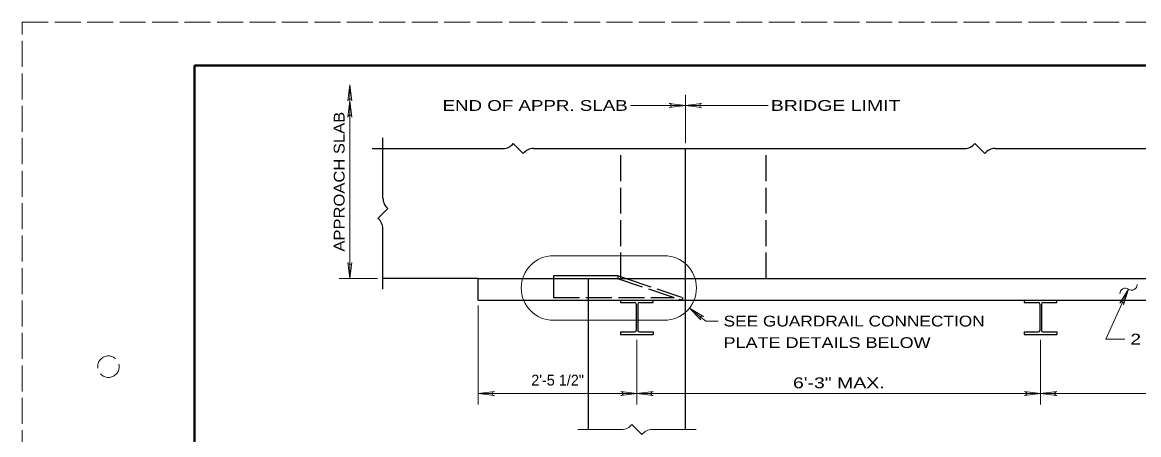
# Model space of a CAD drawing. Extents: x 1285 to 1427, y 1365 to 1427.
# Drawn here: x 1333.33 to 1350.62, y 1420.28 to 1426.67 of the extents above; entities that cross this region are included whole.
import ezdxf
from ezdxf.enums import TextEntityAlignment as Align

# ---------------------------------------------------------------- set-up
doc = ezdxf.new("R2010")
doc.units = 0
doc.header["$LTSCALE"] = 0.067
doc.linetypes.add('LONG_DASHED', pattern=[7.5, 6, -1.5])
for name, color, linetype, lineweight in [('1', 7, 'Continuous', 40), ('42', 7, 'Continuous', 25), ('43', 7, 'Continuous', 25), ('44', 7, 'Continuous', 13), ('47', 7, 'Continuous', 13), ('50', 7, 'LONG_DASHED', 13)]:
    doc.layers.add(name, color=color, linetype=linetype, lineweight=lineweight)
doc.layers.add('41', color=7, linetype='Continuous')

msp = doc.modelspace()

# ---------------------------------------------------------------- linework, layer by layer
at = {"layer": '1', "linetype": 'LONG_DASHED', "lineweight": 13}
msp.add_lwpolyline([(1333.33333, 1426.66667), (1378.66667, 1426.66667), (1378.66667, 1397.33333), (1333.33333, 1397.33333)], close=True, dxfattribs=at)
at = {"layer": '1'}
msp.add_lwpolyline([(1336, 1426), (1378, 1426), (1378, 1398), (1336, 1398)], close=True, dxfattribs=at)
at = {"layer": '42'}
for p, q in [((1338.91656, 1423.94189), (1338.91656, 1424.87889)), ((1340.93544, 1424.78967), (1341.09011, 1424.63478)), ((1348.08167, 1424.78967), (1348.23633, 1424.63478)), ((1338.74989, 1424.71222), (1340.778, 1424.71222)), ((1341.24844, 1424.71222), (1347.92233, 1424.71222)), ((1343.59989, 1422.69833), (1343.59989, 1424.71222)), ((1348.39467, 1424.71222), (1353.05289, 1424.71222)), ((1338.994, 1423.78256), (1338.83911, 1423.62789)), ((1338.91656, 1422.53167), (1338.91656, 1423.46956)), ((1340.39156, 1422.69833), (1338.91656, 1422.69833)), ((1340.39156, 1422.69833), (1356.50211, 1422.69833)), ((1340.39156, 1422.365), (1340.39156, 1422.69833)), ((1341.55756, 1422.69833), (1342.55067, 1422.69833)), ((1342.55756, 1422.74), (1342.55067, 1422.69833)), ((1342.55756, 1422.74), (1342.68256, 1422.69833)), ((1340.39156, 1422.365), (1356.50211, 1422.365)), ((1342.09989, 1420.36067), (1342.09989, 1422.365)), ((1342.59656, 1422.365), (1343.10322, 1422.365)), ((1342.59656, 1422.365), (1342.59656, 1422.32711)), ((1343.10322, 1422.32711), (1343.10322, 1422.365)), ((1343.59989, 1420.36067), (1343.59989, 1422.365)), ((1348.84656, 1422.365), (1349.35322, 1422.365)), ((1348.84656, 1422.365), (1348.84656, 1422.32711)), ((1349.35322, 1422.32711), (1349.35322, 1422.365)), ((1342.59656, 1422.32711), (1342.81322, 1422.32711)), ((1342.83656, 1422.30378), (1342.83656, 1421.89456)), ((1342.86322, 1422.30378), (1342.86322, 1421.89456)), ((1342.88656, 1422.32711), (1343.10322, 1422.32711)), ((1348.84656, 1422.32711), (1349.06322, 1422.32711)), ((1349.08656, 1422.30378), (1349.08656, 1421.89456)), ((1349.11322, 1422.30378), (1349.11322, 1421.89456)), ((1349.13656, 1422.32711), (1349.35322, 1422.32711)), ((1342.59656, 1421.87122), (1342.59656, 1421.83333)), ((1342.59656, 1421.87122), (1342.81322, 1421.87122)), ((1342.59656, 1421.83333), (1343.10322, 1421.83333)), ((1342.88656, 1421.87122), (1343.10322, 1421.87122)), ((1343.10322, 1421.87122), (1343.10322, 1421.83333)), ((1348.84656, 1421.87122), (1348.84656, 1421.83333)), ((1348.84656, 1421.87122), (1349.06322, 1421.87122)), ((1348.84656, 1421.83333), (1349.35322, 1421.83333)), ((1349.13656, 1421.87122), (1349.35322, 1421.87122)), ((1349.35322, 1421.87122), (1349.35322, 1421.83333))]:
    msp.add_line(p, q, dxfattribs=at)
msp.add_lwpolyline([(1342.55756, 1422.74), (1341.55756, 1422.74), (1341.55756, 1422.69833)], dxfattribs=at)
for centre, radius, start, end in [((1340.77707, 1424.91285), 0.20062, 270, 322.10148), ((1347.9233, 1424.91285), 0.20062, 270, 322.10148), ((1341.24848, 1424.51159), 0.20062, 90, 142.10148), ((1348.3947, 1424.51159), 0.20062, 90, 142.10148), ((1339.11718, 1423.94093), 0.20062, 180, 232.10148), ((1338.71593, 1423.46952), 0.20062, 360, 52.10148), ((1342.81322, 1422.30378), 0.02333, 0, 90), ((1342.88656, 1422.30378), 0.02333, 90, 180), ((1349.06322, 1422.30378), 0.02333, 0, 90), ((1349.13656, 1422.30378), 0.02333, 90, 180), ((1342.81322, 1421.89456), 0.02333, 270, 0), ((1342.88656, 1421.89456), 0.02333, 180, 270), ((1349.06322, 1421.89456), 0.02333, 270, 0), ((1349.13656, 1421.89456), 0.02333, 180, 270)]:
    msp.add_arc(centre, radius, start, end, dxfattribs=at)
at = {"layer": '43', "linetype": 'LONG_DASHED'}
for p, q in [((1342.59989, 1422.69833), (1342.59989, 1424.71222)), ((1344.84989, 1422.69833), (1344.84989, 1424.71222)), ((1342.09989, 1422.365), (1342.09989, 1422.69833)), ((1342.55067, 1422.69833), (1343.54433, 1422.36711)), ((1342.68256, 1422.69833), (1343.55756, 1422.40667)), ((1343.59989, 1422.365), (1343.59989, 1422.69833)), ((1343.55756, 1422.40667), (1343.54433, 1422.36711))]:
    msp.add_line(p, q, dxfattribs=at)
msp.add_lwpolyline([(1341.55756, 1422.69833), (1341.55756, 1422.40667), (1343.42567, 1422.40667)], dxfattribs=at)
at = {"layer": '44'}
for p, q in [((1343.59989, 1425.37889), (1342.74789, 1425.37889)), ((1343.59989, 1425.37889), (1343.34989, 1425.41011)), ((1343.84989, 1425.41011), (1343.59989, 1425.37889)), ((1343.59989, 1425.37889), (1343.84989, 1425.34767)), ((1342.77256, 1420.43811), (1342.92722, 1420.28322))]:
    msp.add_line(p, q, dxfattribs=at)
msp.add_lwpolyline([(1343.34989, 1425.34767), (1343.59989, 1425.37889), (1344.88033, 1425.37889)], dxfattribs=at)
for centre, radius, start, end in [((1343.34989, 1425.37889), 0.03122, 270, 90), ((1343.84989, 1425.37889), 0.03122, 90, 270), ((1342.61419, 1420.56129), 0.20062, 270, 322.10148), ((1343.08559, 1420.16004), 0.20062, 90, 142.10148)]:
    msp.add_arc(centre, radius, start, end, dxfattribs=at)
at = {"layer": '47'}
for p, q in [((1338.40578, 1422.69833), (1338.40578, 1425.69833)), ((1343.59989, 1424.79556), (1343.59989, 1425.54556)), ((1341.55756, 1423.05244), (1343.271, 1423.05244)), ((1338.83322, 1422.69833), (1338.23911, 1422.69833)), ((1340.39156, 1422.28167), (1340.39156, 1420.75)), ((1341.55756, 1422.05244), (1343.271, 1422.05244)), ((1342.84989, 1421.75), (1342.84989, 1420.75)), ((1349.09989, 1421.75), (1349.09989, 1420.75)), ((1340.39156, 1420.91667), (1342.84989, 1420.91667)), ((1342.84989, 1420.91667), (1349.09989, 1420.91667)), ((1349.09989, 1420.91667), (1355.34989, 1420.91667)), ((1341.93322, 1420.36067), (1342.61322, 1420.36067)), ((1343.08556, 1420.36067), (1343.76656, 1420.36067))]:
    msp.add_line(p, q, dxfattribs=at)
for points in [[(1338.37456, 1425.44833), (1338.40578, 1425.69833), (1338.437, 1425.44833)], [(1338.37456, 1425.19833), (1338.40578, 1425.44833), (1338.437, 1425.19833)], [(1343.84989, 1425.34767), (1343.59989, 1425.37889), (1343.84989, 1425.41011)], [(1338.437, 1422.94833), (1338.40578, 1422.69833), (1338.37456, 1422.94833)], [(1350.40411, 1421.75967), (1350.10967, 1421.75967), (1350.45989, 1422.53333)], [(1350.32833, 1422.31844), (1350.45989, 1422.53333), (1350.38522, 1422.29267)], [(1344.10733, 1422.03956), (1343.91578, 1422.03956), (1343.66233, 1422.24111)], [(1343.83856, 1422.06111), (1343.66233, 1422.24111), (1343.87744, 1422.10989)], [(1340.64156, 1420.88544), (1340.39156, 1420.91667), (1340.64156, 1420.94789)], [(1342.59989, 1420.94789), (1342.84989, 1420.91667), (1342.59989, 1420.88544)], [(1343.09989, 1420.88544), (1342.84989, 1420.91667), (1343.09989, 1420.94789)], [(1348.84989, 1420.94789), (1349.09989, 1420.91667), (1348.84989, 1420.88544)], [(1349.34989, 1420.88544), (1349.09989, 1420.91667), (1349.34989, 1420.94789)]]:
    msp.add_lwpolyline(points, dxfattribs=at)
for centre, radius, start, end in [((1338.40584, 1425.44836), 0.03122, 0, 180), ((1343.84986, 1425.37895), 0.03122, 90, 270), ((1338.40584, 1425.19836), 0.03122, 0, 180), ((1341.55756, 1422.55244), 0.5, 90, 270), ((1343.27104, 1422.55244), 0.5, 270, 90), ((1338.40572, 1422.9483), 0.03122, 180, 0), ((1350.41073, 1422.46604), 0.08333, 53.85214, 183.85214), ((1350.50904, 1422.60062), 0.08333, 233.85214, 3.85214), ((1350.35686, 1422.30559), 0.03122, 335.64476, 155.64476), ((1343.85801, 1422.08557), 0.03122, 51.50599, 231.50599), ((1340.64152, 1420.91672), 0.03122, 90, 270), ((1342.59992, 1420.91661), 0.03122, 270, 90), ((1343.09986, 1420.91672), 0.03122, 90, 270), ((1348.84992, 1420.91661), 0.03122, 270, 90), ((1349.34986, 1420.91672), 0.03122, 90, 270)]:
    msp.add_arc(centre, radius, start, end, dxfattribs=at)
at = {"layer": '50'}
msp.add_circle((1334.66667, 1421.33333), 0.16667, dxfattribs=at)

# ---------------------------------------------------------------- texts
at = {"layer": '41', "width": 1.15}
msp.add_text('APPROACH SLAB', height=0.1667, rotation=90, dxfattribs=at).set_placement((1338.32244, 1424.19839), align=Align.CENTER)
at = {"layer": '41'}
for s, width, p in [('SEE GUARDRAIL CONNECTION ', 1.2, (1344.19067, 1421.95622)), ('2 - TS 8 x 4 x 5/16 TUBING', 1.35, (1350.48744, 1421.67633)), ('PLATE DETAILS BELOW', 1.25, (1344.19067, 1421.62289))]:
    msp.add_text(s, height=0.1667, dxfattribs=dict(at, width=width)).set_placement(p)
msp.add_text('2\'-5 1/2"', height=0.1667, dxfattribs=at).set_placement((1341.62061, 1421.04167), align=Align.CENTER)
at = {"layer": '44', "width": 1.3}
msp.add_text('END OF APPR. SLAB', height=0.1667, dxfattribs=at).set_placement((1342.70622, 1425.29556), align=Align.RIGHT)
at = {"layer": '44', "width": 1.35}
msp.add_text('BRIDGE LIMIT', height=0.1667, dxfattribs=at).set_placement((1344.922, 1425.29556))
msp.add_text('6\'-3" MAX.', height=0.1667, dxfattribs=at).set_placement((1345.97489, 1421), align=Align.CENTER)

doc.saveas('drawing.dxf')
